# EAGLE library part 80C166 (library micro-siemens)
MICROPROCESSOR/PERIPHERAL DEVICE
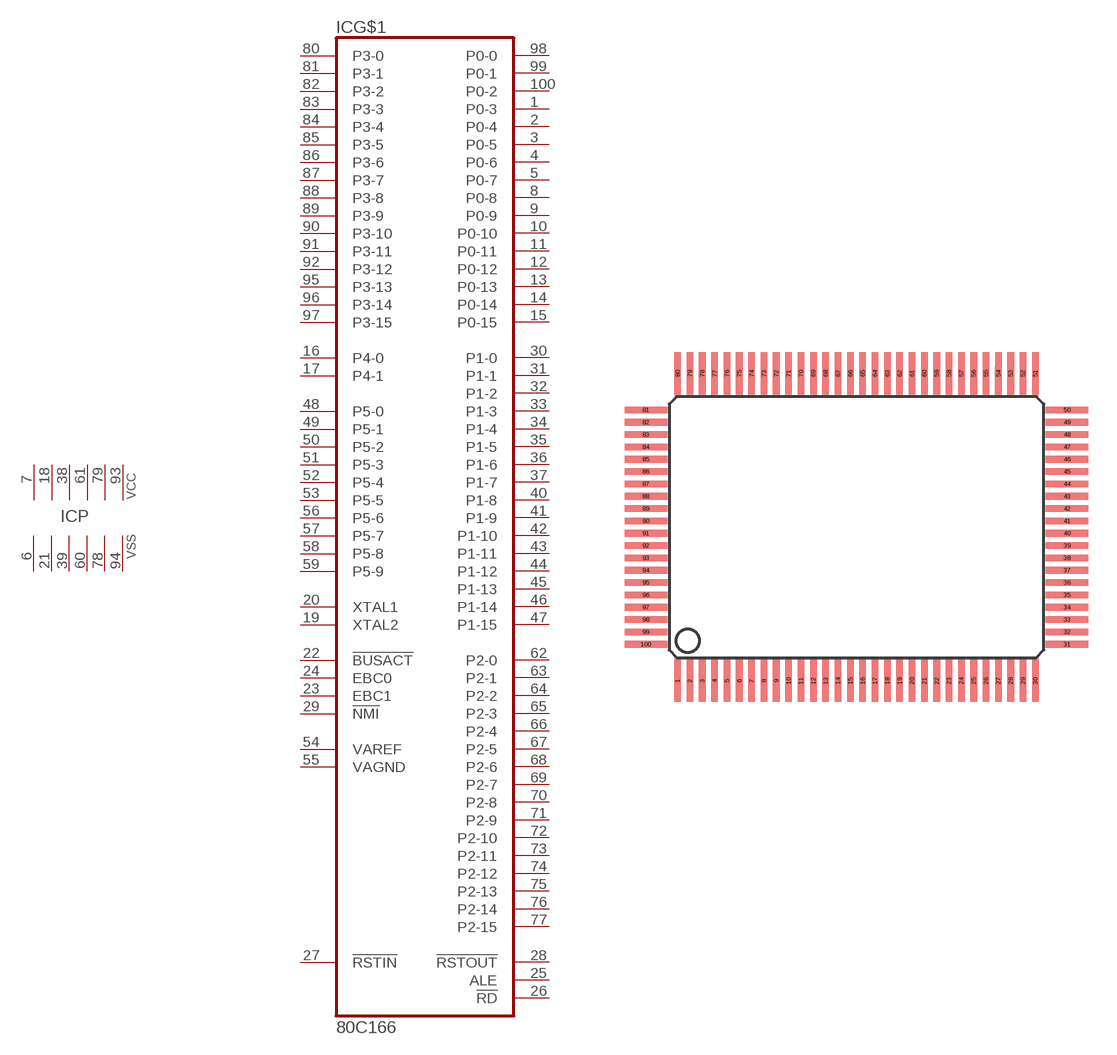
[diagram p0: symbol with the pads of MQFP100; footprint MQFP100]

Designator prefix IC; gates G$1=80C166 P=6_VCCVSS

## 80C166 (OC_FARNELL: unknown; OC_NEWARK: unknown)  [MQFP100]
1  G$1:P0-3
2  G$1:P0-4
3  G$1:P0-5
4  G$1:P0-6
5  G$1:P0-7
6  P:VSS  pwr
7  P:VCC  pwr
8  G$1:P0-8
9  G$1:P0-9
10  G$1:P0-10
11  G$1:P0-11
12  G$1:P0-12
13  G$1:P0-13
14  G$1:P0-14
15  G$1:P0-15
16  G$1:P4-0
17  G$1:P4-1
18  P:VCC  pwr
19  G$1:XTAL2  out
20  G$1:XTAL1  in
21  P:VSS  pwr
22  G$1:!BUSACT  in
23  G$1:EBC1  in
24  G$1:EBC0  in
25  G$1:ALE  out
26  G$1:!RD  out
27  G$1:!RSTIN  in
28  G$1:!RSTOUT  out
29  G$1:!NMI  in
30  G$1:P1-0
31  G$1:P1-1
32  G$1:P1-2
33  G$1:P1-3
34  G$1:P1-4
35  G$1:P1-5
36  G$1:P1-6
37  G$1:P1-7
38  P:VCC  pwr
39  P:VSS  pwr
40  G$1:P1-8
41  G$1:P1-9
42  G$1:P1-10
43  G$1:P1-11
44  G$1:P1-12
45  G$1:P1-13
46  G$1:P1-14
47  G$1:P1-15
48  G$1:P5-0  in
49  G$1:P5-1  in
50  G$1:P5-2  in
51  G$1:P5-3  in
52  G$1:P5-4  in
53  G$1:P5-5  in
54  G$1:VAREF  pas
55  G$1:VAGND  pas
56  G$1:P5-6  in
57  G$1:P5-7  in
58  G$1:P5-8  in
59  G$1:P5-9  in
60  P:VSS  pwr
61  P:VCC  pwr
62  G$1:P2-0
63  G$1:P2-1
64  G$1:P2-2
65  G$1:P2-3
66  G$1:P2-4
67  G$1:P2-5
68  G$1:P2-6
69  G$1:P2-7
70  G$1:P2-8
71  G$1:P2-9
72  G$1:P2-10
73  G$1:P2-11
74  G$1:P2-12
75  G$1:P2-13
76  G$1:P2-14
77  G$1:P2-15
78  P:VSS  pwr
79  P:VCC  pwr
80  G$1:P3-0
81  G$1:P3-1
82  G$1:P3-2
83  G$1:P3-3
84  G$1:P3-4
85  G$1:P3-5
86  G$1:P3-6
87  G$1:P3-7
88  G$1:P3-8
89  G$1:P3-9
90  G$1:P3-10
91  G$1:P3-11
92  G$1:P3-12
93  P:VCC  pwr
94  P:VSS  pwr
95  G$1:P3-13
96  G$1:P3-14
97  G$1:P3-15
98  G$1:P0-0
99  G$1:P0-1
100  G$1:P0-2

## Footprint MQFP100 (pad centres in mm)
Metric Quad Flat Pack
smd 0.35 x 2.2: 1 -9.425,-8.1; 2 -8.775,-8.1; 3 -8.125,-8.1; 4 -7.475,-8.1; 5 -6.825,-8.1; 6 -6.175,-8.1; 7 -5.525,-8.1; 8 -4.875,-8.1; 9 -4.225,-8.1; 10 -3.575,-8.1; 11 -2.925,-8.1; 12 -2.275,-8.1; 13 -1.625,-8.1; 14 -0.975,-8.1; 15 -0.325,-8.1; 16 0.325,-8.1; 17 0.975,-8.1; 18 1.625,-8.1; 19 2.275,-8.1; 20 2.925,-8.1; 21 3.575,-8.1; 22 4.225,-8.1; 23 4.875,-8.1; 24 5.525,-8.1; 25 6.175,-8.1; 26 6.825,-8.1; 27 7.475,-8.1; 28 8.125,-8.1; 29 8.775,-8.1; 30 9.425,-8.1; 51 9.425,8.1; 52 8.775,8.1; 53 8.125,8.1; 54 7.475,8.1; 55 6.825,8.1; 56 6.175,8.1; 57 5.525,8.1; 58 4.875,8.1; 59 4.225,8.1; 60 3.575,8.1; 61 2.925,8.1; 62 2.275,8.1; 63 1.625,8.1; 64 0.975,8.1; 65 0.325,8.1; 66 -0.325,8.1; 67 -0.975,8.1; 68 -1.625,8.1; 69 -2.275,8.1; 70 -2.925,8.1; 71 -3.575,8.1; 72 -4.225,8.1; 73 -4.875,8.1; 74 -5.525,8.1; 75 -6.175,8.1; 76 -6.825,8.1; 77 -7.475,8.1; 78 -8.125,8.1; 79 -8.775,8.1; 80 -9.425,8.1
smd 2.2 x 0.35: 31 11.1,-6.175; 32 11.1,-5.525; 33 11.1,-4.875; 34 11.1,-4.225; 35 11.1,-3.575; 36 11.1,-2.925; 37 11.1,-2.275; 38 11.1,-1.625; 39 11.1,-0.975; 40 11.1,-0.325; 41 11.1,0.325; 42 11.1,0.975; 43 11.1,1.625; 44 11.1,2.275; 45 11.1,2.925; 46 11.1,3.575; 47 11.1,4.225; 48 11.1,4.875; 49 11.1,5.525; 50 11.1,6.175; 81 -11.1,6.175; 82 -11.1,5.525; 83 -11.1,4.875; 84 -11.1,4.225; 85 -11.1,3.575; 86 -11.1,2.925; 87 -11.1,2.275; 88 -11.1,1.625; 89 -11.1,0.975; 90 -11.1,0.325; 91 -11.1,-0.325; 92 -11.1,-0.975; 93 -11.1,-1.625; 94 -11.1,-2.275; 95 -11.1,-2.925; 96 -11.1,-3.575; 97 -11.1,-4.225; 98 -11.1,-4.875; 99 -11.1,-5.525; 100 -11.1,-6.175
